Omron CX-Programmer project 新工程 (CX-Programmer 5.00)

# PLC 新PLC1: CPM2* 

## Program 新程序1 (no task)
Local symbols
X行程大 LR0.00 BOOL
Y_TEMP DM1920 UDINT_BCD
Y累加值 DM1924 UDINT_BCD
Y终点坐标 DM87 UDINT_BCD
x步进 202.14 BOOL
x步进禁止 LR0.12 BOOL
y步进 202.15 BOOL
y累加进位 LR0.02 BOOL
直线累加器 DM1960 UDINT_BCD

### Section 段1

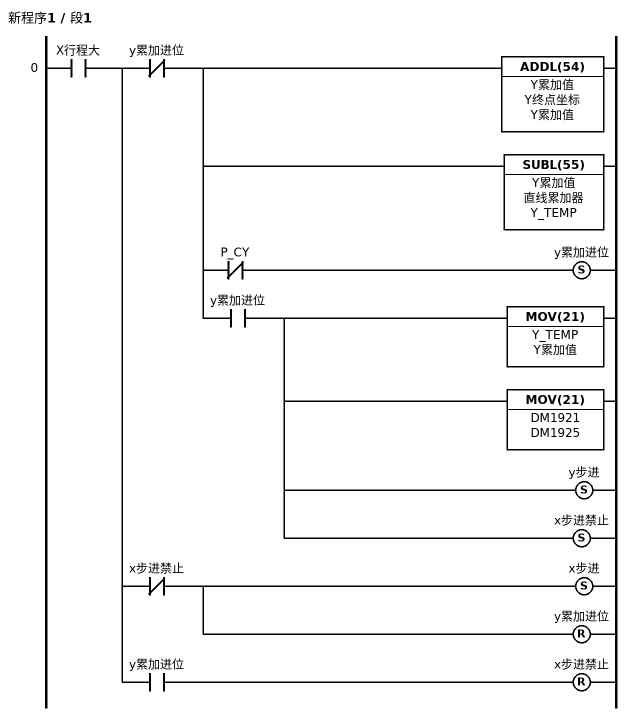
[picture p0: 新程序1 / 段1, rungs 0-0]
; rung 0
LD X行程大
OUT TR0
ANDNOT y累加进位
OUT TR1
ADDL(54) Y累加值 Y终点坐标 Y累加值
SUBL(55) Y累加值 直线累加器 Y_TEMP
ANDNOT P_CY
SET y累加进位
LD TR1
AND y累加进位
MOV(21) Y_TEMP Y累加值
MOV(21) DM1921 DM1925
SET y步进
SET x步进禁止
LD TR0
ANDNOT x步进禁止
SET x步进
RSET y累加进位
LD TR0
AND y累加进位
RSET x步进禁止

### Section END
; rung 0
END(01)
